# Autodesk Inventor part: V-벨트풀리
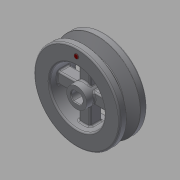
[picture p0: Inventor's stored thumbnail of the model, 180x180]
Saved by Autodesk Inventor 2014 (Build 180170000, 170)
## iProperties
Created: 2018-01
Part Number: V-벨트풀리
Material: 스테인리스강
Document SubType Name: Modeling
Designer: mduedu
Density: 1 g/cm^3
Appearance: 기본값
Author: mduedu
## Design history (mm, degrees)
sketch "스케치1"
  geometry: C1 r 30 at (0, 0); 1 further point
  constraints: 1 centre point, 1 coincident
  dimensions: "d0" = 60 diameter of C1
extrude "돌출1" new body sketch "스케치1" stored distance "d1" = 19; taper "d2" = 0 deg
sketch "스케치2"
  geometry: L1 (30, -9.5)-(-30, -9.5) reference; L2 (-30, -9.5)-(-30, 9.5) reference; L3 (-30, 9.5)-(30, 9.5) reference; L4 (30, 9.5)-(30, -9.5) reference; L5 (-30, 0)-(30, 0); L6 (30, 4.825)-(21, 2.074); L7 (21, 2.074)-(21, -2.074); L8 (21, -2.074)-(30, -4.825); L9 (30, -4.825)-(30, 4.825); L10 (27.3, 9.5)-(27.3, -9.5); L11 (0, -13.3)-(0, 13.3) reference; 4 further points
  constraints: 12 end point, 9 point on line, 3 midpoint, 2 perpendicular, 1 collinear, 1 symmetric about line
  dimensions: "d3" = 34 deg angle of L8 L6; "d4" = 2.7 distance between parallel lines of L10 L4; "d5" = 6.3 distance between parallel lines of L7 L10; "d6" = 8 distance of point (27.3, -4) point (27.3, 4)
revolve "회전1" sketch "스케치2" stored, may be unused: angle "d7" = 90 deg
fillet "모깎기1" dims "d8" = 0.2
fillet "모깎기2" dims "d9" = 0.5
fillet "모깎기3" dims "d10" = 1
sketch "스케치3"
  geometry: C1 r 19 at (0, 0); 1 further point
  constraints: 1 centre point, 1 coincident
  dimensions: "d11" = 38 diameter of C1
extrude "돌출2" cut sketch "스케치3" stored distance "d12" = 19; taper "d13" = 0 deg
sketch "스케치4"
  geometry: C1 r 7 at (0, 0); 1 further point
  constraints: 1 centre point, 1 coincident
  dimensions: "d14" = 14 diameter of C1
extrude "돌출3" join sketch "스케치4" stored distance "d15" = 19; taper "d16" = 0 deg
sketch "스케치5"
  geometry: L1 (0, 7)-(0, 19); L2 (4, 5.745)-(4, 18.574); L3 (-4, 5.745)-(-4, 18.574); C1 r 21 at (0, 0) reference; A1 r 19 centre (0, 0) between (0, 19) and (-4, 18.574) reference; A2 r 7 centre (0, 0) between (0, 7) and (-4, 5.745) reference; 1 further point
  constraints: 6 end point, 6 point on circle, 2 parallel, 1 point on line, 1 vertical, 1 other
  dimensions: "d17" = 8 distance between parallel lines of L2 L3
extrude "돌출4" join sketch "스케치5" stored distance "d18" = 8; taper "d19" = 0 deg
fillet "모깎기4" dims "d20" = 1
fillet "모깎기5" dims "d24" = 1
fillet "모깎기6" dims "d25" = 1
hole "구멍1" diameter "d28" = 8; stored, may be unused: countersink angle "d32" = 90 deg, drill point angle "d34" = 118 deg; dims "d26" = 10, "d27" = 10, "d29" = 6, "d30" = 4, "d31" = 2, "d33" = 8
sketch "스케치6"
  geometry: L1 (-2.332, -3.25)-(2.332, -3.25); L2 (2.332, 3.25)-(-2.332, 3.25); L3 (-2.332, -3.25)-(2.332, 3.25); L4 (2.332, -3.25)-(-2.332, 3.25); A1 r 4 centre (0, 0) between (2.332, 3.25) and (-2.332, 3.25) reference; A2 r 4 centre (0, 0) between (2.332, 3.25) and (-2.332, 3.25); A3 r 4 centre (0, 0) between (-2.332, -3.25) and (2.332, -3.25); 1 further point
  constraints: 8 end point, 7 point on circle, 2 centre point, 2 coincident, 2 midpoint, 1 horizontal, 1 parallel
  dimensions: "d35" = 6.5 distance of L1.end L2.start
extrude "돌출5" join sketch "스케치6" stored distance "d37" = 8; taper "d38" = 0 deg
chamfer "모따기1" distance "d39" = 0.5; stored, may be unused: second distance "d40" = 2, angle "d41" = 45 deg
chamfer "모따기2" distance "d42" = 0.5; stored, may be unused: second distance "d43" = 2, angle "d44" = 45 deg
sketch "스케치7" dims "d45" = 50
  geometry: C1 r 1.5 at (0, 25); 2 further points
  constraints: 2 vertical alignment, 1 centre point, 1 coincident, 2 other
  dimensions: "d46" = 3 diameter of C1
extrude "돌출6" join sketch "스케치7" distance "d47" = 0.5; taper "d48" = 0 deg
fillet "모깎기7" dims "d49" = 0.1
node "솔리드1"
pattern_circular "원형 패턴1" dims angle "d22" = 360 deg
node "절단 모서리 투영1"
node "절단 모서리 투영2"
